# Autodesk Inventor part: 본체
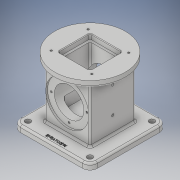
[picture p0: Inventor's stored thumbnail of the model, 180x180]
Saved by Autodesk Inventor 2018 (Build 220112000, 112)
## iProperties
Created: 2021-05
Part Number: 본체
Material: Generic
Document SubType Name: Modeling
Designer: 1class6
Density: 1 g/cm^3
Appearance: Default
Author: 1class6
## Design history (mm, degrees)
sketch "스케치1"
  geometry: L1 (62.5, 62.5)-(-62.5, 62.5); L2 (-62.5, 62.5)-(-62.5, -62.5); L3 (-62.5, -62.5)-(62.5, -62.5); L4 (62.5, -62.5)-(62.5, 62.5); L5 (62.5, 62.5)-(-62.5, -62.5); L6 (-62.5, 62.5)-(62.5, -62.5); 1 further point
  constraints: 12 end point, 2 midpoint, 2 parallel, 1 horizontal, 1 perpendicular
  dimensions: "d0" = 125 distance between parallel lines of L2 L4; "d1" = 125 distance between parallel lines of L1 L3 (= d0)
extrude "돌출1" new body sketch "스케치1" distance "d2" = 10; taper "d3" = 0 deg
sketch "스케치2"
  geometry: L1 (-37, -37)-(37, -37); L2 (37, -37)-(37, 37); L3 (37, 37)-(-37, 37); L4 (-37, 37)-(-37, -37); L5 (-37, -37)-(37, 37); L6 (37, -37)-(-37, 37); 1 further point
  constraints: 12 end point, 2 midpoint, 2 parallel, 1 horizontal, 1 perpendicular
  dimensions: "d4" = 74 distance between parallel lines of L2 L4; "d5" = 74 distance between parallel lines of L1 L3 (= d4)
extrude "돌출2" join sketch "스케치2" distance "d6" = 88; taper "d7" = 0 deg
sketch "스케치3"
  geometry: C1 r 57.5 at (0, 0); 1 further point
  constraints: 1 centre point, 1 coincident
  dimensions: "d8" = 115 diameter of C1
extrude "돌출3" join sketch "스케치3" distance "d9" = 10; taper "d10" = 0 deg
sketch "스케치5"
  geometry: L1 (0, 0)-(0, 18); L2 (0, 18)-(24.826, 18); L3 (24.826, 18)-(28, 0); L4 (62.5, 0)-(-62.5, 0) reference; L5 (0, 0)-(28, 0)
  constraints: 8 end point, 1 collinear, 1 perpendicular, 1 point on line, 1 vertical
  dimensions: "d11" = 18 distance between parallel lines of L4 L2; "d12" = 80 deg angle of L4 L3; "d13" = 56 diameter of L3.end L1
revolve "회전1" sketch "스케치5" stored, may be unused: angle "d14" = 90 deg
sketch "스케치6"
  geometry: L1 (-25.5, -10)-(99.5, -10) reference; C1 r 24 at (37, 44); 2 further points
  constraints: 1 centre point, 1 midpoint, 1 vertical alignment
  dimensions: "d15" = 54 distance from line of C1.centre L1; "d16" = 48 diameter of C1
extrude "돌출4" cut sketch "스케치6" extent not by distance; stored distance "d17" = 0; taper "d18" = 0 deg
sketch "스케치7"
  geometry: C1 r 24 at (37, 44) reference; C2 r 35 at (37, 44); 1 further point
  constraints: 1 centre point, 1 coincident
  dimensions: "d19" = 70 diameter of C2
extrude "돌출5" cut sketch "스케치7" distance "d20" = 3; taper "d21" = 0 deg
sketch "스케치8"
  geometry: L1 (-26, -26)-(26, -26); L2 (26, -26)-(26, 26); L3 (26, 26)-(-26, 26); L4 (-26, 26)-(-26, -26); L5 (-26, -26)-(26, 26); L6 (26, -26)-(-26, 26); C1 r 57.5 at (0, 0) reference
  constraints: 12 end point, 2 midpoint, 2 parallel, 1 horizontal, 1 perpendicular
  dimensions: "d22" = 52 distance between parallel lines of L2 L4; "d23" = 52 distance between parallel lines of L1 L3 (= d22)
extrude "돌출6" cut sketch "스케치8" distance "d24" = 8; taper "d25" = 0 deg
sketch "스케치9"
  geometry: L1 (-22, -22)-(22, -22); L2 (22, -22)-(22, 22); L3 (22, 22)-(-22, 22); L4 (-22, 22)-(-22, -22); L5 (-22, -22)-(22, 22); L6 (22, -22)-(-22, 22); 1 further point
  constraints: 12 end point, 2 midpoint, 2 parallel, 1 horizontal, 1 perpendicular
  dimensions: "d26" = 44 distance between parallel lines of L2 L4; "d27" = 44 distance between parallel lines of L1 L3 (= d26)
extrude "돌출7" cut sketch "스케치9" distance "d28" = 74; taper "d29" = 0 deg
sketch "스케치11" dims "d30" = 58
  geometry: C1 r 35 at (0, 0) reference; 3 further points
  constraints: 1 coincident, 1 vertical alignment, 2 other
hole "구멍1" sketch "스케치11" at (0, 29) diameter "d31" = 3.242; stored, may be unused: countersink angle "d35" = 90 deg, drill point angle "d37" = 118 deg; dims "d32" = 8, "d33" = 4, "d34" = 2, "d36" = 10
sketch "스케치12"
  geometry: L1 (-33, -30)-(33, -30); L2 (33, -30)-(33, 30); L3 (33, 30)-(-33, 30); L4 (-33, 30)-(-33, -30); L5 (-33, -30)-(33, 30); L6 (33, -30)-(-33, 30); C1 r 57.5 at (0, 0) reference
  constraints: 12 end point, 2 midpoint, 2 parallel, 1 horizontal, 1 perpendicular
  dimensions: "d41" = 66 distance between parallel lines of L2 L4; "d42" = 60 distance between parallel lines of L1 L3
hole "구멍2" sketch "스케치12" at (33, 30), (33, -30), (-33, -30), (-33, 30) diameter "d43" = 3.242; stored, may be unused: countersink angle "d47" = 90 deg, drill point angle "d49" = 118 deg; dims "d44" = 8, "d45" = 4, "d46" = 2, "d48" = 10
fillet "모깎기1" dims "d50" = 12
sketch "스케치14"
  geometry: A1 r 12 centre (50.5, 50.5) between (62.5, 50.5) and (50.5, 62.5) reference; 1 further point
hole "구멍3" sketch "스케치14" at (50.5, 50.5) diameter "d51" = 9; stored, may be unused: countersink angle "d55" = 90 deg, drill point angle "d57" = 0 deg; dims "d52" = 8, "d53" = 4, "d54" = 2, "d56" = 10
sketch "스케치15"
  geometry: A1 r 12 centre (-50.5, 50.5) between (-50.5, 62.5) and (-62.5, 50.5) reference; A2 r 12 centre (-50.5, -50.5) between (-62.5, -50.5) and (-50.5, -62.5) reference; A3 r 12 centre (50.5, -50.5) between (50.5, -62.5) and (62.5, -50.5) reference; 3 further points
  constraints: 1 horizontal alignment, 1 other
hole "구멍4" sketch "스케치15" at (-50.5, -50.5), (50.5, -50.5), (-50.5, 50.5) diameter "d58" = 9; stored, may be unused: countersink angle "d62" = 90 deg, drill point angle "d64" = 0 deg; dims "d59" = 8, "d60" = 4, "d61" = 2, "d63" = 10
fillet "모깎기2" dims "d65" = 3
fillet "모깎기3" dims "d69" = 3
chamfer "모따기2" distance "d70" = 1; stored, may be unused: second distance "d71" = 2, angle "d72" = 45 deg
sketch "스케치17"
  geometry: L1 (-84.5, -13)-(16.5, -13) reference; 5 further points
  constraints: 2 midpoint, 2 vertical alignment
  dimensions: "d73" = 37 distance from line of point (-34, 24) L1; "d74" = 43 distance of point (-34, 67) point (-34, 24)
hole "구멍5" sketch "스케치17" at (-34, 24), (-34, 67) diameter "d75" = 4.134; stored, may be unused: countersink angle "d79" = 90 deg, drill point angle "d81" = 0 deg; dims "d76" = 30, "d77" = 4, "d78" = 2, "d80" = 30
sketch "스케치18"
  geometry: 2 further points
  constraints: 1 vertical alignment, 1 other
  dimensions: "d82" = 55 distance of point (0, 0) point (0, -55)
feature "엠보싱1" sketch "스케치18" dims "d0" = 125, "d1" = 125 (= d0), "d83" = 0.5, "d84" = 0
node "솔리드1"
mirror "미러1"
pattern_circular "원형 패턴1" dims angle "d39" = 360 deg
mirror "미러2"
